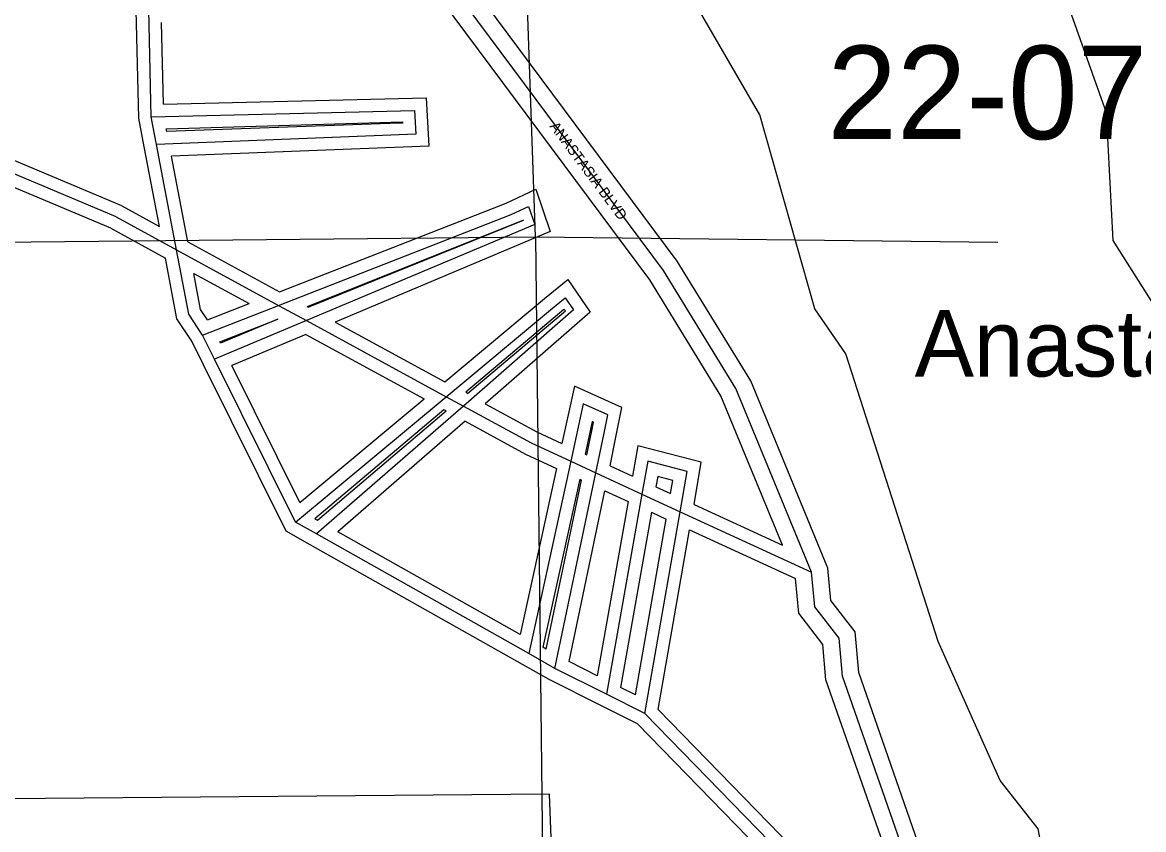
# Model space of a CAD drawing. Extents: x 418523 to 616617, y 1878279 to 2196743.
# Drawn here: x 566933 to 569632, y 2012645 to 2014588 of the extents above; entities that cross this region are included whole.
import ezdxf

# ---------------------------------------------------------------- set-up
doc = ezdxf.new("R2010")
doc.units = 0
for name, color, linetype in [('Level 1', 7, 'Continuous'), ('Level 2', 7, 'Continuous'), ('Level 22', 7, 'Continuous'), ('Level 23', 7, 'Continuous'), ('Level 31', 7, 'Continuous'), ('Level 32', 7, 'Continuous'), ('Level 34', 7, 'Continuous'), ('Level 5', 7, 'Continuous'), ('Level 57', 7, 'Continuous'), ('Level 8', 7, 'Continuous')]:
    doc.layers.add(name, color=color, linetype=linetype)

msp = doc.modelspace()

# ---------------------------------------------------------------- linework, layer by layer
at = {"layer": 'Level 1'}
for p, q in [((568168.027, 2014072.298), (568147.358, 2014670.906)), ((562889.28, 2014020.741), (568168.027, 2014072.298)), ((568168.027, 2014072.298), (568225.789, 2008858.623)), ((568168.027, 2014072.298), (569280.542, 2014059.696))]:
    msp.add_line(p, q, dxfattribs=at)
at = {"layer": 'Level 22'}
for points in [[(568832.354, 2013265.078), (568650.204, 2013707.359), (568475.922, 2013991.431), (567973.269, 2014667.59), (567969.999, 2014671.386)], [(569619.639, 2011495.826), (569519.67, 2011579.341), (569262.559, 2012096.71), (569063.974, 2012564.119), (568906.562, 2013014.704), (568898.539, 2013106.366), (568840.396, 2013181.781), (568832.354, 2013265.078)]]:
    msp.add_lwpolyline(points, dxfattribs=at)
at = {"layer": 'Level 23'}
for points in [[(568762.205, 2013330.367), (568614.435, 2013689.168), (568442.757, 2013968.995), (567942.024, 2014642.571), (567917.078, 2014671.529)], [(568871.6, 2013274.826), (568685.973, 2013725.551), (568509.086, 2014013.866), (568020.39, 2014671.25)], [(569641.039, 2011530.071), (569551.756, 2011604.658), (569298.909, 2012113.446), (569101.304, 2012578.551), (568945.974, 2013023.175), (568937.365, 2013121.516), (568879.105, 2013197.086), (568871.6, 2013274.826)], [(569522.769, 2011524.63), (569487.584, 2011554.023), (569226.208, 2012079.973), (569026.644, 2012549.686), (568867.149, 2013006.234), (568859.711, 2013091.215), (568801.688, 2013166.477), (568793.637, 2013249.865)]]:
    msp.add_lwpolyline(points, dxfattribs=at)
at = {"layer": 'Level 31'}
for p, q in [((567242.907, 2014361.336), (567236.874, 2014618.459)), ((567242.907, 2014361.336), (567876.534, 2014376.531)), ((567255.741, 2014294.756), (567242.907, 2014361.336)), ((567303.937, 2014040.805), (567255.741, 2014294.756)), ((567158.964, 2014120.071), (566800.854, 2014270.771)), ((567158.964, 2014120.071), (567303.937, 2014040.805)), ((567549.572, 2013907.11), (568109.208, 2014125.773)), ((567303.937, 2014040.805), (567549.572, 2013907.11)), ((567366.515, 2013835.912), (567549.572, 2013907.11)), ((567549.572, 2013907.11), (567616.679, 2013870.581)), ((567953.163, 2013687.212), (568208.826, 2013900.429)), ((567616.679, 2013870.581), (567395.534, 2013777.656)), ((567616.679, 2013870.581), (567953.163, 2013687.212)), ((567395.534, 2013777.656), (567366.515, 2013835.912)), ((567590.468, 2013385.16), (567395.534, 2013777.656)), ((567590.468, 2013385.16), (567953.163, 2013687.212)), ((567953.163, 2013687.212), (567994.314, 2013664.93)), ((567994.314, 2013664.93), (567640.479, 2013357.036)), ((568313.108, 2013504.153), (568332.988, 2013599.748)), ((568252.951, 2013531.936), (568151.681, 2013068.877)), ((568252.951, 2013531.936), (568313.108, 2013504.153)), ((568214.673, 2013033.451), (568313.108, 2013504.153)), ((568313.108, 2013504.153), (568424.239, 2013452.975)), ((568516.055, 2013410.57), (568532.769, 2013507.627)), ((568424.239, 2013452.975), (568338.774, 2012970.967)), ((568424.239, 2013452.975), (568516.055, 2013410.57)), ((568431.216, 2012924.561), (568516.055, 2013410.57)), ((568516.055, 2013410.57), (568832.354, 2013265.078)), ((567640.479, 2013357.036), (567590.468, 2013385.16)), ((568151.681, 2013068.877), (567640.479, 2013357.036)), ((568214.673, 2013033.451), (568151.681, 2013068.877)), ((568338.774, 2012970.967), (568214.673, 2013033.451)), ((568431.216, 2012924.561), (568338.774, 2012970.967))]:
    msp.add_line(p, q, dxfattribs=at)
for points in [[(567876.534, 2014376.531), (567879.564, 2014319.066), (567255.741, 2014294.756)], [(568109.208, 2014125.773), (568151.411, 2014145.673), (568166.203, 2014101.635), (567616.679, 2013870.581)], [(567366.515, 2013835.912), (567333.357, 2013886.177), (567303.937, 2014040.805)], [(568208.826, 2013900.429), (568239.314, 2013925.448), (568259.529, 2013896.307), (567994.314, 2013664.93)], [(567994.314, 2013664.93), (568157.336, 2013576.169), (568252.951, 2013531.936)], [(568332.988, 2013599.748), (568341.65, 2013643.73), (568283.076, 2013670.054), (568252.951, 2013531.936)], [(568532.769, 2013507.627), (568438.056, 2013532.22), (568424.239, 2013452.975)], [(569077.589, 2011488.747), (569053.914, 2011930.649), (568946.4, 2012306.201), (568822.03, 2012523.239), (568431.216, 2012924.561)]]:
    msp.add_lwpolyline(points, dxfattribs=at)
at = {"layer": 'Level 32'}
for p, q in [((567212.974, 2014358.122), (567206.882, 2014617.755)), ((567272.196, 2014392.047), (567267.589, 2014588.469)), ((567272.196, 2014392.047), (567904.958, 2014407.222)), ((567226.283, 2014289.077), (567212.974, 2014358.121)), ((567280.323, 2014325.736), (567279.079, 2014332.194)), ((567172.013, 2014147.128), (566812.49, 2014298.422)), ((567262.625, 2014097.584), (567226.267, 2014289.162)), ((567330.762, 2014060.36), (567291.709, 2014266.133)), ((567145.916, 2014093.011), (566796.029, 2014240.252)), ((567172.013, 2014147.127), (567262.624, 2014097.584)), ((567551.655, 2013940.132), (568097.339, 2014153.344)), ((567145.916, 2014093.012), (567277.114, 2014021.278)), ((567330.762, 2014060.361), (567551.655, 2013940.132)), ((567345.254, 2013984.16), (567478.479, 2013911.648)), ((567378.219, 2013872.652), (567478.479, 2013911.647)), ((567620.549, 2013902.631), (567618.35, 2013903.828)), ((567949.612, 2013723.313), (568189.612, 2013923.469)), ((567408.024, 2013819.866), (567547.464, 2013874.099)), ((567547.528, 2013874.065), (567409.846, 2013816.211)), ((567547.465, 2013874.1), (567547.529, 2013874.065)), ((567685.779, 2013867.09), (567949.612, 2013723.313)), ((567368.681, 2013764.28), (567340.473, 2013820.909)), ((567409.846, 2013816.211), (567408.025, 2013819.866)), ((567614.997, 2013837.331), (567436.619, 2013762.377)), ((567614.997, 2013837.331), (567900.029, 2013682.002)), ((567567.709, 2013363.539), (567368.665, 2013764.311)), ((567600.448, 2013432.512), (567436.619, 2013762.377)), ((567600.448, 2013432.512), (567900.028, 2013682.001)), ((567947.664, 2013656.074), (567636.745, 2013393.555)), ((567643.124, 2013389.968), (567953.155, 2013653.101)), ((567953.155, 2013653.101), (567947.664, 2013656.074)), ((567998.281, 2013628.611), (567692.234, 2013362.301)), ((568291.421, 2013547.215), (568303.553, 2013605.546)), ((568347.341, 2013521.416), (568362.424, 2013593.95)), ((568287.396, 2013549.073), (568291.42, 2013547.215)), ((568347.341, 2013521.416), (568401.381, 2013496.53)), ((568549.534, 2013428.192), (568567.019, 2013529.729)), ((568218.499, 2013514.818), (568131.048, 2013114.946)), ((568274.28, 2013489.04), (568185.732, 2013084.147)), ((568193.689, 2013079.671), (568278.856, 2013486.926)), ((568274.281, 2013489.039), (568278.857, 2013486.926)), ((568457.755, 2013470.541), (568493.129, 2013454.204)), ((568493.129, 2013454.204), (568498.521, 2013485.524)), ((568248.758, 2013049.878), (568334.765, 2013461.15)), ((568334.764, 2013461.15), (568390.656, 2013435.411)), ((568390.657, 2013435.411), (568316.27, 2013015.886)), ((568549.534, 2013428.192), (568762.205, 2013330.367)), ((567636.745, 2013393.555), (567643.123, 2013389.968)), ((568446.985, 2013409.423), (568372.218, 2012987.746)), ((568408.604, 2012969.481), (568482.536, 2013393.006)), ((568446.986, 2013409.423), (568482.536, 2013393.006)), ((567625.775, 2013330.886), (567567.709, 2013363.539)), ((568131.049, 2013114.946), (567692.234, 2013362.301)), ((568463.408, 2012934.506), (568538.911, 2013367.035)), ((568538.911, 2013367.035), (568793.637, 2013249.865)), ((568136.949, 2013042.742), (567625.748, 2013330.901)), ((568193.689, 2013079.671), (568185.732, 2013084.146)), ((568200.567, 2013006.965), (568136.975, 2013042.728)), ((568316.269, 2013015.886), (568248.758, 2013049.878)), ((568325.283, 2012944.171), (568200.568, 2013006.964)), ((568408.604, 2012969.481), (568372.218, 2012987.746)), ((568413.246, 2012900.013), (568325.314, 2012944.155))]:
    msp.add_line(p, q, dxfattribs=at)
for points in [[(567904.959, 2014407.222), (567911.125, 2014290.273), (567291.709, 2014266.133)], [(567279.079, 2014332.194), (567847.449, 2014349.261), (567848.109, 2014345.84)], [(567848.109, 2014345.84), (567839.472, 2014345.84), (567280.323, 2014325.736)], [(568097.339, 2014153.344), (568169.115, 2014187.19), (568203.512, 2014084.777), (567685.779, 2013867.09)], [(567620.549, 2013902.631), (568138.688, 2014112.134), (567618.35, 2013903.828)], [(567340.473, 2013820.909), (567305.007, 2013874.67), (567277.114, 2014021.278)], [(567378.219, 2013872.652), (567361.706, 2013897.685), (567345.254, 2013984.16)], [(568189.794, 2013923.621), (568245.425, 2013969.273), (568299.481, 2013891.348), (568046.523, 2013670.663)], [(568004.147, 2013695.183), (568000.594, 2013699.391), (568236.242, 2013898.316)], [(568004.147, 2013695.183), (568239.794, 2013894.108), (568236.242, 2013898.316)], [(568362.424, 2013593.95), (568375.693, 2013661.322), (568261.645, 2013712.576), (568231.61, 2013574.865)], [(568046.523, 2013670.663), (568170.821, 2013602.986), (568231.609, 2013574.865)], [(567998.28, 2013628.611), (568143.85, 2013549.352), (568218.499, 2013514.818)], [(568303.553, 2013605.546), (568307.609, 2013626.137), (568304.508, 2013627.531), (568287.396, 2013549.073)], [(568567.018, 2013529.729), (568414.093, 2013569.436), (568401.381, 2013496.53)], [(568498.522, 2013485.524), (568462.02, 2013495.002), (568457.755, 2013470.541)], [(569106.005, 2011519.135), (569083.69, 2011935.643), (568974.241, 2012317.958), (568846.172, 2012541.449), (568463.408, 2012934.506)], [(569045.968, 2011518.213), (569024.137, 2011925.655), (568918.56, 2012294.444), (568797.889, 2012505.029), (568413.246, 2012900.013)]]:
    msp.add_lwpolyline(points, dxfattribs=at)
at = {"layer": 'Level 5'}
for points in [[(569750.749, 2011978.684), (569426.974, 2012388.21), (569377.769, 2012646.805), (569286.464, 2012763.806), (569137.485, 2013097.752), (568914.627, 2013790.386), (568839.954, 2013899.016), (568708.072, 2014366.276), (568533.993, 2014666.941)], [(569436.123, 2014667.421), (569541.742, 2014371.906), (569557.438, 2014063.419), (569673.524, 2013879.636)]]:
    msp.add_lwpolyline(points, dxfattribs=at)
at = {"layer": 'Level 8'}
msp.add_lwpolyline([(568247.423, 2009781.606), (568240.417, 2010115.614), (568235.393, 2011474.645), (568236.387, 2011794.651), (568236.386, 2011832.652), (568201.369, 2012730.672), (566894.339, 2012719.656), (566882.322, 2013628.677), (566862.314, 2014034.686), (566014.294, 2014023.676), (565950.294, 2014022.675), (565593.285, 2014017.67), (565546.284, 2014017.67), (565543.282, 2014141.672), (565535.275, 2014507.681), (565532.272, 2014673.684)], dxfattribs=at)

# ---------------------------------------------------------------- texts
at = {"layer": 'Level 2'}
msp.add_text('22-07-30', height=225, dxfattribs=at).set_placement((568870.794, 2014307.431))
at = {"layer": 'Level 34'}
msp.add_text('ANASTASIA BLVD', height=25, rotation=306.625947, dxfattribs=at).set_placement((568200.832, 2014338.053))
at = {"layer": 'Level 57'}
msp.add_text('Anastasia State Park', height=160, dxfattribs=at).set_placement((569080.68, 2013735.976))

doc.saveas('drawing.dxf')
